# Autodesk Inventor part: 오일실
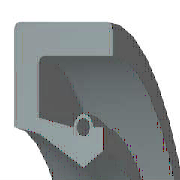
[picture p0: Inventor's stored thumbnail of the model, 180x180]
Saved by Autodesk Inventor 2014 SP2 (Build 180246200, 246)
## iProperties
IsCustomPart: 1
Created: 2015-12
Part Number: 오일실
Material: 일반
Description: 오일-실
Document SubType Name: Modeling
Standard: KS B 2804
Designer: mdu
Standards Organization: KS
Language: ko-KR
Size Designation: S - 15 30 7
Categories: <MemberInstance><Categories><Category DisplayName="샤프트 부품" InternalName="7f7aeb1f-a693-4053-b835-cee3144e0d98" Mnemonic="SHFT"><Category DisplayName="실링" Intern
Density: 1 g/cm^3
Appearance: 기본값
Mass: 1.76736 g
Surface Area: 26.6454 cm^2
Volume: 1.76736 cm^3
Author: mdu
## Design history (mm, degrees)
revolve "본체" stored, may be unused: angle "d17" = 90 deg
revolve "스프링1" stored, may be unused: angle "d18" = 90 deg
body "Solid1"
sketch "스케치1"
  geometry: L1 (0, 15)-(7, 15); L2 (7, 15)-(7, 13.75); L3 (7, 13.75)-(1.75, 13.75); L4 (0, 15)-(0, 9.6); L5 (0, 9.6)-(1.75, 9.25); L6 (1.75, 9.25)-(4.9, 7.5); L7 (4.9, 7.5)-(0, 7.5); L8 (6.3, 8.375)-(6.3, 9.6); L9 (0, 0)-(9.586, 0) reference; L10 (4.9, 7.5)-(6.3, 8.375); L11 (0, 18)-(0, -3) reference; L12 (-1.917, 0)-(11.503, 0) reference; L13 (4.2, 9.6)-(1.75, 10.09); L14 (1.75, 10.09)-(1.75, 13.75); L15 (6.3, 9.6)-(5.6, 9.6); C1 r 0.455 at (4.9, 9.6); A1 r 0.7 centre (4.9, 9.6) between (5.6, 9.6) and (4.2, 9.6)
  constraints: 26 end point, 5 horizontal alignment, 4 perpendicular, 2 centre point, 2 collinear, 2 horizontal, 2 parallel, 2 point on circle, 2 point on line, 2 vertical alignment, 1 coincident
  dimensions: "d0" = 30 diameter of L1 L9 (= SD2); "d1" = 16.75 diameter of L8.start L9 (= ABDM); "d2" = 1.25 distance of L1.end L2.end (computed from SD); "d3" = 0.91 diameter of C1 (= SPDI); "d4" = 1.4 diameter of A1 (= SPDA); "d5" = 15 diameter of L6.end L9 (= NND); "d6" = 18.5 diameter of L5.end L9 (= TKDM); "d7" = 19.2 diameter of L4.end L9 (= HLDM); "d8" = 4.9 distance from line of C1.centre L4 (= SPDST); "d9" = 6.3 distance between parallel lines of L8 L4 (= SDI); "d10" = 7 distance between parallel lines of L2 L4 (= SWDT); "d12" = 1.75 distance between parallel lines of L14 L4 (= SD)
fillet "모깎기1" dims "d11" = 0.3 (= RR)
other parameters: "SD2" = 30 [user parameter; used in 1 equation term], "SWDT" = 7 [user parameter; used in 1 equation term], "RR" = 0.3 [user parameter; used in 1 equation term], "SD" = 1.75 [user parameter; used in 2 equation terms], "NND" = 15 [user parameter; used in 1 equation term], "SPDA" = 1.4 [user parameter; used in 1 equation term], "SPDI" = 0.91 [user parameter; used in 1 equation term], "TKDM" = 18.5 [user parameter; used in 1 equation term], "HLDM" = 19.2 [user parameter; used in 1 equation term], "ABDM" = 16.75 [user parameter; used in 1 equation term], "SDI" = 6.3 [user parameter; used in 1 equation term], "SPDST" = 4.9 [user parameter; used in 1 equation term], "d13" = 0, "d14" = 0, "d15" = 0, "LAB" = 0.35 [user parameter]
